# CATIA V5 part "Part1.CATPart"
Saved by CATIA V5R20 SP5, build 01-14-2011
Part number: Part1
Bounding box of the stored display mesh (mm): x -70 to 70, y -80 to 80, z -90 to 30
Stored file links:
  E:\180122237\shuichi\Part1.CATPart
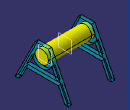
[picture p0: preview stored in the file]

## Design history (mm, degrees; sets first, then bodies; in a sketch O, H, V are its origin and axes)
Body1 (main body)
  Sketch1 on yz-plane, origin (0, 0, 0), H (0, 1, 0), V (0, 0, 1)
    circle A1 centre (0, 0) radius 20
    point P1 (20, 0)
    coincidence: A1 P1, P1 H
  Pad1: profile Sketch1, direction (1, 0, 0), length 70, mirrored extent
Body2
  Plane1: type Offset, RefPlane yz-plane, Offset 60
  Sketch2 on Plane1, origin (60, 0, 0), H (0, 1, 0), V (0, 0, 1)
    line L1 (20, 30) -> (-20, 30)
    line L2 (-20, 30) -> (-80, -90)
    line L3 (-80, -90) -> (-70, -90)
    line L4 (80, -90) -> (20, 30)
    circle A1 centre (0, 0) radius 20
    point P5 (20, 0)
    point P6 (70, -90)
    line L5 (70, -90) -> (50, -50)
    line L6 (-70, -90) -> (-50, -50)
    arc A2 centre (0, 2.5) radius 32.5 from (30, -10) to (-30, -10) cw
    point P11 (0, -30)
    line L7 (70, -90) -> (80, -90)
    line L8 (-45, -40) -> (45, -40)
    point P12 (-45, -40)
    point P13 (45, -40)
    line L9 (50, -50) -> (-50, -50)
    line L10 (45, -40) -> (30, -10)
    line L11 (-45, -40) -> (-30, -10)
    horizontal: L1 H, L3 H, L7 H, L8 H, L9 H
    coincidence: A1 P5, P5 H, P6 L3, A2 P11, P11 V, L3 L7, P12 L6, P13 L5, L5 L10, L6 L11
    parallelism: L5 L4, L6 L2
  Pad2: profile Sketch2, direction (1, 0, 0), length 10
  Mirror1: of Pad2, about yz-plane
